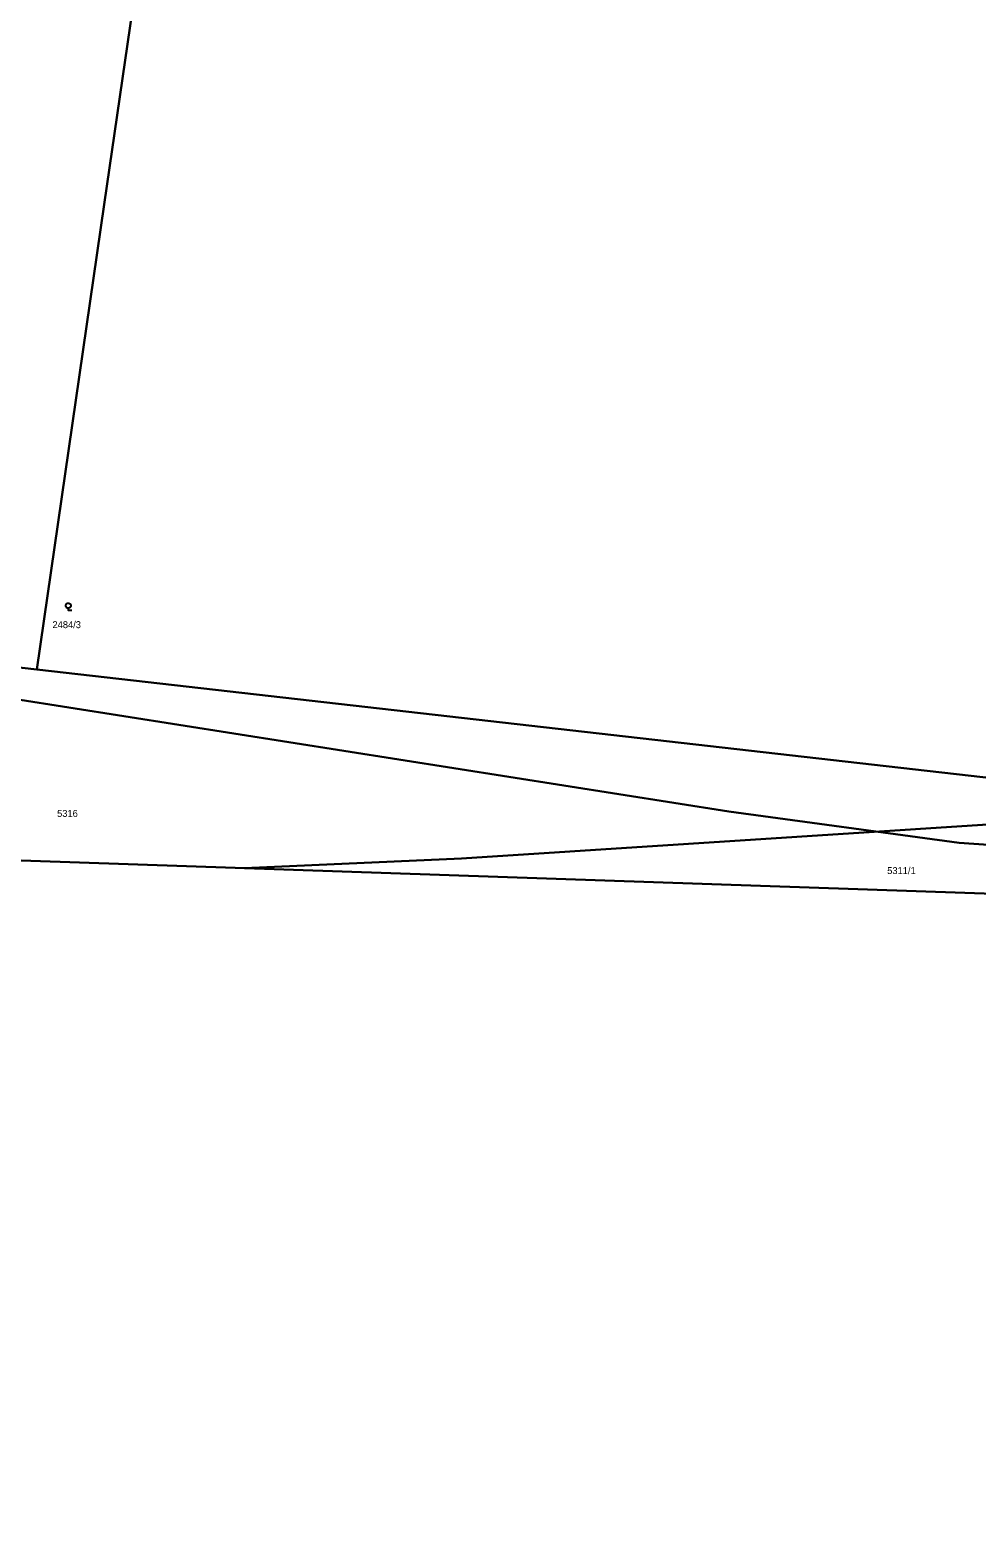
# Model space of a CAD drawing. Extents: x -439750 to -439180, y -1258684 to -1258308.
# Drawn here: x -439469.4 to -439415, y -1258535.8 to -1258449.2 of the extents above; entities that cross this region are included whole.
import ezdxf

# ---------------------------------------------------------------- set-up
doc = ezdxf.new("R2010")
doc.units = 0
doc.layers.add('KATASTER', color=7, linetype='Continuous')
doc.layers.add('UOV', color=7, linetype='Continuous')

# ---------------------------------------------------------------- blocks, each defined once
blk = doc.blocks.new('305')
blk.add_lwpolyline([(0, 0.53), (-0.19, 0.53), (-0.53, 0.72), (-0.72, 1.06), (-0.72, 1.45), (-0.53, 1.79), (-0.19, 1.98), (0.2, 1.98), (0.54, 1.79), (0.73, 1.45), (0.73, 1.06), (0.54, 0.72), (0.2, 0.53), (0.01, 0.53), (0.01, 0), (1.01, 0)])

msp = doc.modelspace()

# ---------------------------------------------------------------- linework, layer by layer
at = {"layer": 'KATASTER'}
for points in [[(-439441.83, -1258441.42), (-439442.45, -1258432.5), (-439434.74, -1258431.72), (-439415.05, -1258427.42), (-439387, -1258423.44), (-439387.21, -1258424.13), (-439393.11, -1258458.67), (-439398.93, -1258492.76), (-439399.2, -1258493.87), (-439399.61, -1258493.83), (-439469.01, -1258485.93), (-439465.13, -1258459.21), (-439462.74, -1258442.73), (-439442, -1258444.33)], [(-439515.19, -1258481.93), (-439514.85, -1258480.71), (-439469.01, -1258485.93), (-439399.61, -1258493.83), (-439399.2, -1258493.87), (-439399.97, -1258496.98), (-439415.96, -1258495.89), (-439429.22, -1258494.1), (-439470.33, -1258487.62), (-439485.72, -1258487.41), (-439495.92, -1258486.32), (-439503.22, -1258485.2)]]:
    msp.add_lwpolyline(points, close=True, dxfattribs=at)
for points in [[(-439462.74, -1258442.73), (-439465.13, -1258459.21), (-439469.01, -1258485.93), (-439514.85, -1258480.71), (-439509.68, -1258462.08), (-439512.86, -1258458.3), (-439516.51, -1258455.4), (-439520.66, -1258452.66), (-439525.5, -1258450.78), (-439531.73, -1258450.85), (-439536.69, -1258451.87), (-439541.07, -1258454.21), (-439546.64, -1258459.47)], [(-439546.64, -1258459.47), (-439541.07, -1258454.21), (-439536.69, -1258451.87), (-439531.73, -1258450.85), (-439525.5, -1258450.78), (-439520.66, -1258452.66), (-439516.51, -1258455.4), (-439512.86, -1258458.3), (-439509.68, -1258462.08), (-439514.85, -1258480.71), (-439515.19, -1258481.93), (-439503.22, -1258485.2), (-439495.92, -1258486.32), (-439485.72, -1258487.41), (-439470.33, -1258487.62), (-439429.22, -1258494.1), (-439415.96, -1258495.89), (-439399.97, -1258496.98), (-439400.54, -1258499.28), (-439484.47, -1258496.42), (-439507.21, -1258497.49), (-439520.19, -1258486.95), (-439538.17, -1258484.88), (-439548.5, -1258497.7)], [(-439548.5, -1258497.7), (-439538.17, -1258484.88), (-439520.19, -1258486.95), (-439507.21, -1258497.49), (-439484.47, -1258496.42), (-439400.54, -1258499.28), (-439387.09, -1258499.74), (-439411.19, -1258562.66), (-439413.56, -1258566.65), (-439437.77, -1258626.82), (-439438.12, -1258627.38), (-439482.75, -1258611.76), (-439518.67, -1258591.95), (-439550.54, -1258581.84), (-439567.51, -1258574.36), (-439597.45, -1258561.13)]]:
    msp.add_lwpolyline(points, dxfattribs=at)
at = {"layer": 'UOV'}
for points in [[(-439484.47, -1258496.42), (-439507.21, -1258497.49), (-439513.68, -1258492.23), (-439512.62, -1258492.23), (-439510.04, -1258487.61), (-439512.85, -1258480.94), (-439399.2, -1258493.87), (-439444.59, -1258496.79), (-439457.07, -1258497.35)], [(-439398.93, -1258492.76), (-439390.58, -1258499.62), (-439400.54, -1258499.28), (-439457.07, -1258497.35), (-439444.59, -1258496.79), (-439399.2, -1258493.87)]]:
    msp.add_lwpolyline(points, close=True, dxfattribs=at)

# ---------------------------------------------------------------- block references
at = {"layer": 'KATASTER', "xscale": 0.2, "yscale": 0.20000000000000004}
msp.add_blockref('305', (-439467.196, -1258482.519), dxfattribs=at)

# ---------------------------------------------------------------- texts
at = {"layer": 'KATASTER'}
msp.add_text('2484/3', height=0.4, dxfattribs=at).set_placement((-439468.104, -1258483.554))
at = {"layer": 'UOV'}
for s, p in [('5316', (-439467.838, -1258494.405)), ('5311/1', (-439420.104, -1258497.69))]:
    msp.add_text(s, height=0.4, dxfattribs=at).set_placement(p)

doc.saveas('drawing.dxf')
